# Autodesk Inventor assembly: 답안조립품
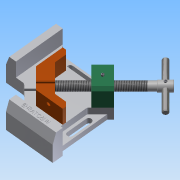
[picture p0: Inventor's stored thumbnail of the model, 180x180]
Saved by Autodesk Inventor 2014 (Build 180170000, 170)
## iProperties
Created: 2020-05
Part Number: 답안조립품
Document SubType Name: Assembly
Designer: NET
Author: NET
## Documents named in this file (11)
- C:\Users\NET\Desktop\700506V1043\답안조립품.iam
- C:\Users\NET\Desktop\700506V1043\답안본체.ipt
- C:\Users\NET\Desktop\700506V1043\조.ipt
- C:\Users\NET\Desktop\700506V1043\부시.ipt
- C:\Users\NET\Desktop\700506V1043\리드스크류.ipt
- C:\Users\NET\Desktop\700506V1043\평행 핀 2.5x24.ipt
- C:\Users\NET\Desktop\700506V1043\서포트.ipt
- C:\Users\NET\Desktop\700506V1043\볼트 M4x16.ipt
- C:\Users\NET\Desktop\700506V1043\핸들.ipt
- C:\Users\NET\Desktop\700506V1043\멈춤나사 M4x5.ipt
- C:\Users\NET\Desktop\700506V1043\멈춤나사 M4x10.ipt
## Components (1 placed, 1 different names)
1. 핸들:1
